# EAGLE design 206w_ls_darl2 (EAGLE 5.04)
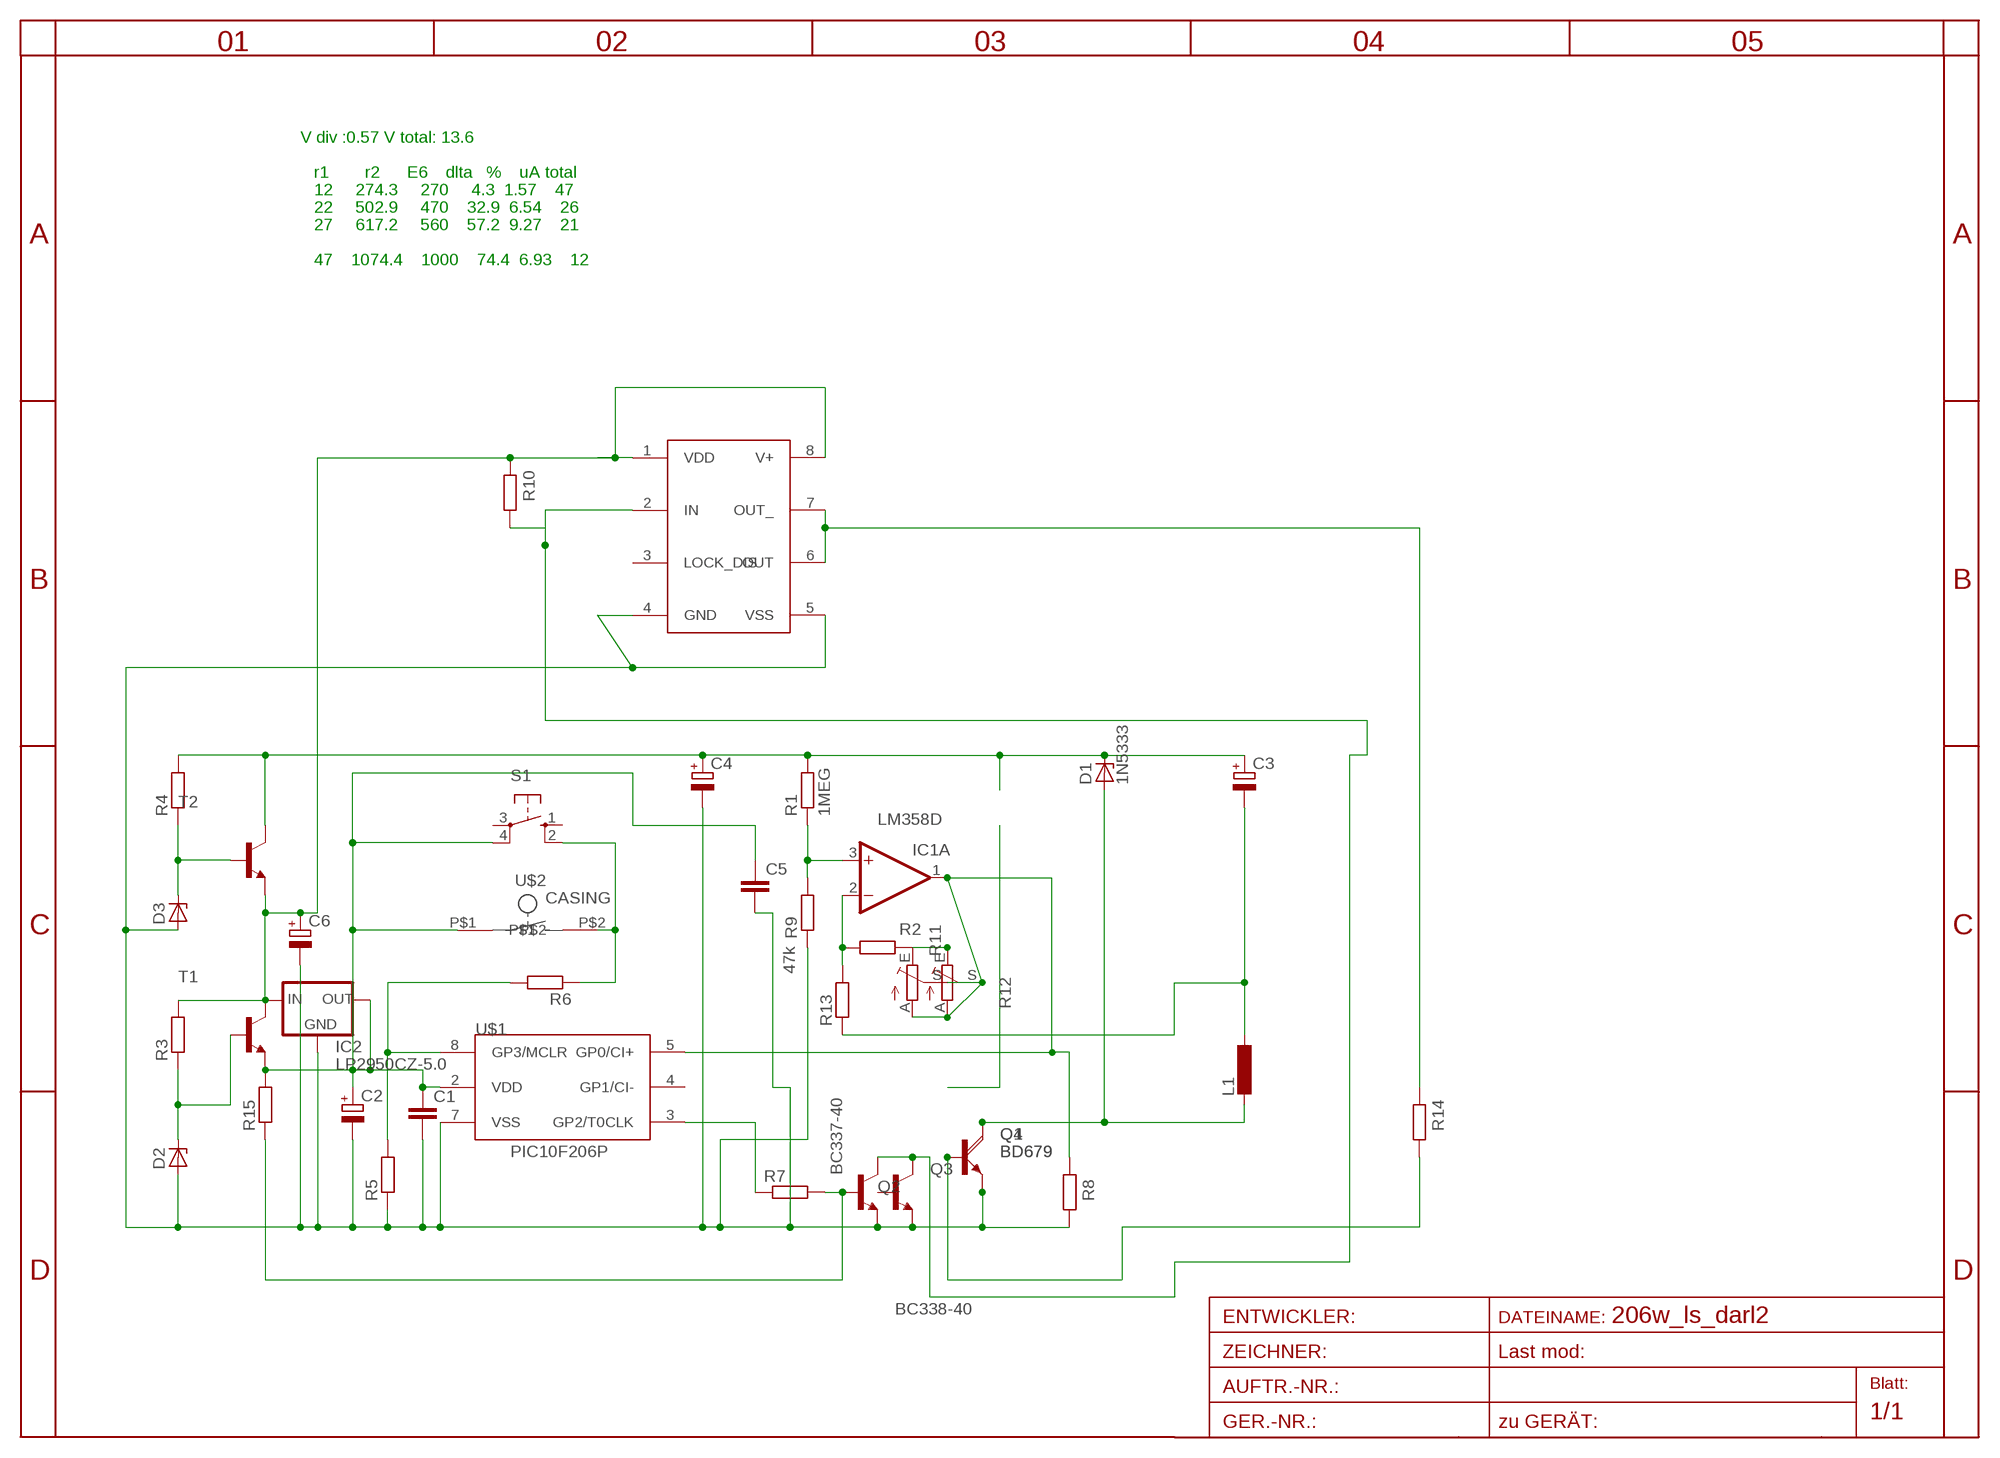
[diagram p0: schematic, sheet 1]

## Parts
C1  C-EU025-025X050  [C025-025X050]
C2  CPOL-EUE3.5-8  [E3,5-8]
C3  CPOL-EUE5-8.5  [E5-8,5]
C4  CPOL-EUE5-8.5  [E5-8,5]
C5  C-EU050-024X044  [C050-024X044]
C6  CPOL-EUE3.5-8  [E3,5-8]
D1  1N5333  [C1702-15]
D2  ZENER-DIODEZD-7.5  [ZDIO-7.5]
D3  ZENER-DIODEZD-7.5  [ZDIO-7.5]
IC1  LM358D  [SO08]
IC2  LP2950CZ-5.0  [TO92]
IC3  TC4432X  [SO-08]
L1  L-EU0207/10  [0207/10]
Q1  BD679  [TO126AV]
Q2  BC337-40  [TO92]
Q3  BC338-40  [TO92-EBC]
Q4  BD679  [TO126AV]
R1  1MEG  R-EU_0207/12  [0207/12]
R2  R-EU_0204/7  [0204/7]
R3  R-EU_0204/7  [0204/7]
R4  R-EU_0207/10  [0207/10]
R5  R-EU_0204/7  [0204/7]
R6  R-EU_0204/7  [0204/7]
R7  R-EU_0207/15  [0207/15]
R8  R-EU_0204/7  [0204/7]
R9  47k  R-EU_0204/7  [0204/7]
R10  R-EU_0204/7  [0204/7]
R11  TRIM_EU-CA6V  [CA6V]
R12  TRIM_EU-LI15  [LI15]
R13  R-EU_0207/40  [0207/40]
R14  R-EU_0204/2V  [0204V]
R15  R-EU_0204/5  [0204/5]
S1  10-XX  [B3F-10XX]
T1  -NPN-TO92-BCE  [TO92-BCE]
T2  -NPN-TO92-BCE  [TO92-BCE]
U$1  PIC10F206P  [DIL8]
U$2  CASING  [CASING]

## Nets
BB: IC3.2(IN) Q2.3(C) Q3.C R10.1
HOTSPOT: D1.A L1.2 Q1.C Q4.C
N$1: IC1.1(A:OUT) R8.2 R11.A R11.S R12.A R12.S U$1.5(GP0/CI+)
N$2: R2.1 R11.E R12.E
N$3: Q1.B Q4.B R14.1
N$5: R5.2 R6.2 U$1.8(GP3/MCLR)
N$6: D2.C R3.1 T1.B
N$7: R6.1 S1.2(S1) U$2.P$2
N$8: IC1.3(A:+IN) R1.1 R9.2
N$9: R7.1 U$1.3(GP2/T0CLK)
N$10: Q2.2(B) R7.2 R15.1
N$11: IC3.6(OUT) IC3.7(OUT_) R14.2
N$12: D3.C R4.1 T2.B
N$15: IC1.2(A:-IN) R2.2 R13.2
V60: C3.+ C4.+ D1.C R1.2 R4.2 T2.C
V+: C1.1 C2.+ C5.1 IC2.1(OUT) R15.2 S1.4(P1) T1.E U$1.2(VDD) U$2.P$1
V-: C1.2 C2.- C4.- C5.2 C6.- D2.A D3.A IC2.2(GND) IC3.4(GND) IC3.5(VSS) Q1.E Q2.1(E) Q3.E Q4.E R5.1 R8.1 R9.1 U$1.7(VSS)
VCC: C6.+ IC2.3(IN) IC3.1(VDD) IC3.8(V+) R3.2 R10.2 T1.C T2.E
VOUT: C3.- L1.1 R13.1
Unconnected: IC1.5(B:+IN) IC1.6(B:-IN) IC1.7(B:OUT) IC3.3(LOCK_DIS) Q3.B S1.1(S) S1.3(P) U$1.4(GP1/CI-)

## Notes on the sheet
- V div :0.57 V total: 13.6
- r1        r2      E6    dlta   %    uA total
- 12     274.3     270     4.3  1.57    47
- 22     502.9     470    32.9  6.54    26
- 27     617.2     560    57.2  9.27    21
- 47    1074.4    1000    74.4  6.93    12

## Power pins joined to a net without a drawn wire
V+: IC1.8(P:V+)
V-: IC1.4(P:V-)

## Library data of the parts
C1 C5 = rcl:C-EU: CAPACITOR, European symbol
C2-C4 C6 = rcl:CPOL-EU: POLARIZED CAPACITOR, European symbol
D1 = diode-1:1N5333: Z DIODE
D2 D3 = diode-1:ZENER-DIODE: Z-Diode
IC1 = linear4:LM358: OP AMP
IC2 = v-reg:LP2950?*: Source: http://cache.national.com/ds/LP/LP2950.pdf
IC3 = microchip:TC4432
L1 = rcl:L-EU: INDUCTOR, European symbol
Q1 Q4 = transistor-power:BD679: NPN DARLINGTON TRANSISTOR
Q2 = transistor-npn:BC337*: NPN Transistor
Q3 = transistor-npn:BC338*: NPN Transistor
R1-R6 R8-R10 R14 R15 = rcl:R-EU_: RESISTOR, European symbol
R7 R13 = rcl-2:R-EU_: RESISTOR, European symbol
R11 R12 = pot:TRIM_EU-: POTENTIOMETER
S1 = switch-omron:10-XX: OMRON SWITCH
T1 T2 = transistor-neu-to92:*-NPN-: NPN Transistror
U$1 = microchip-5:PIC10F2*: uPC nW 0,25/0,5k Program Flash memory Comparator
U$2 = button:CASING

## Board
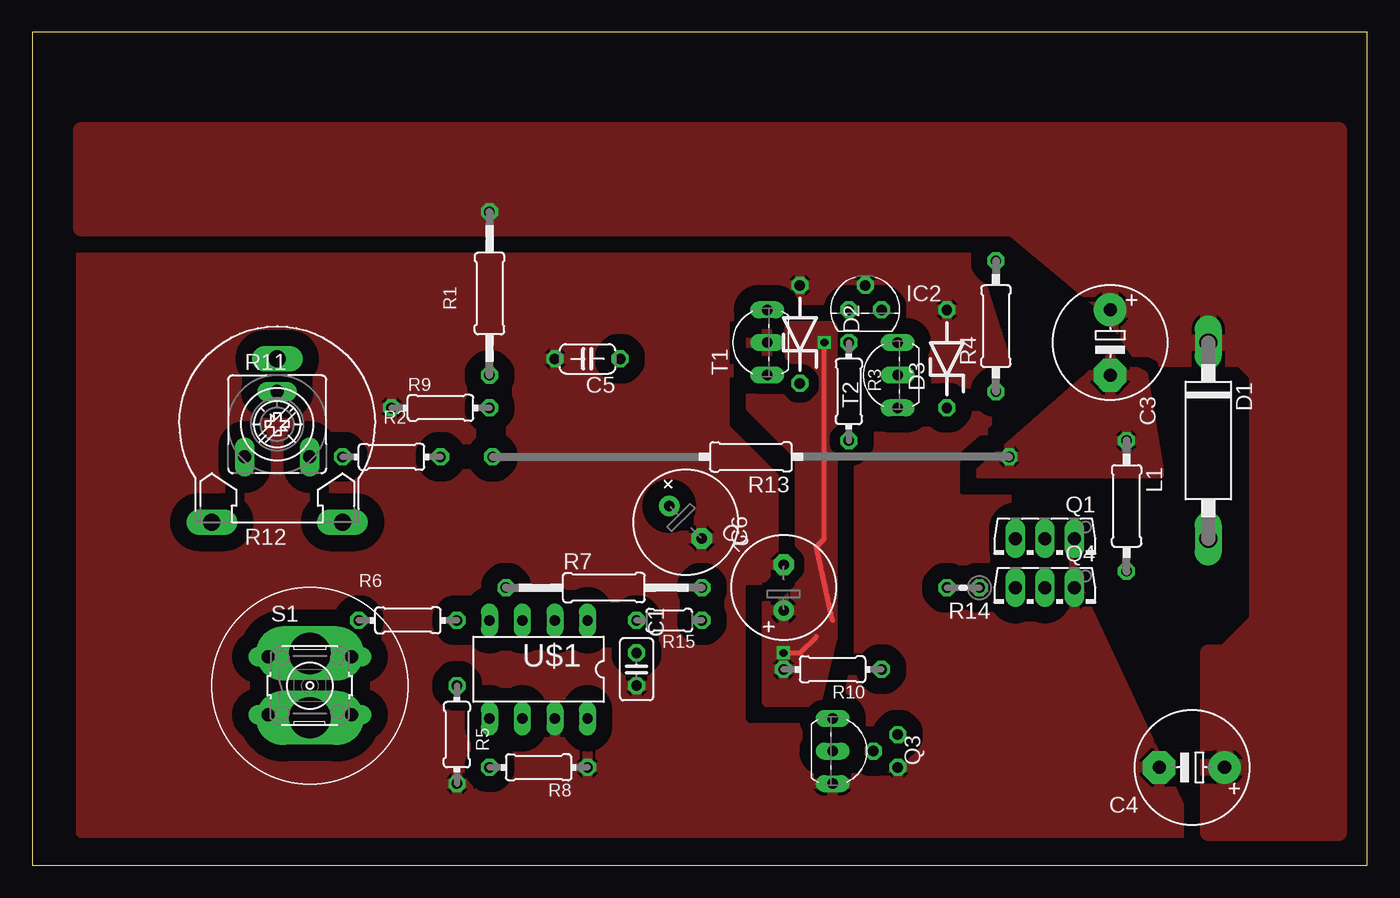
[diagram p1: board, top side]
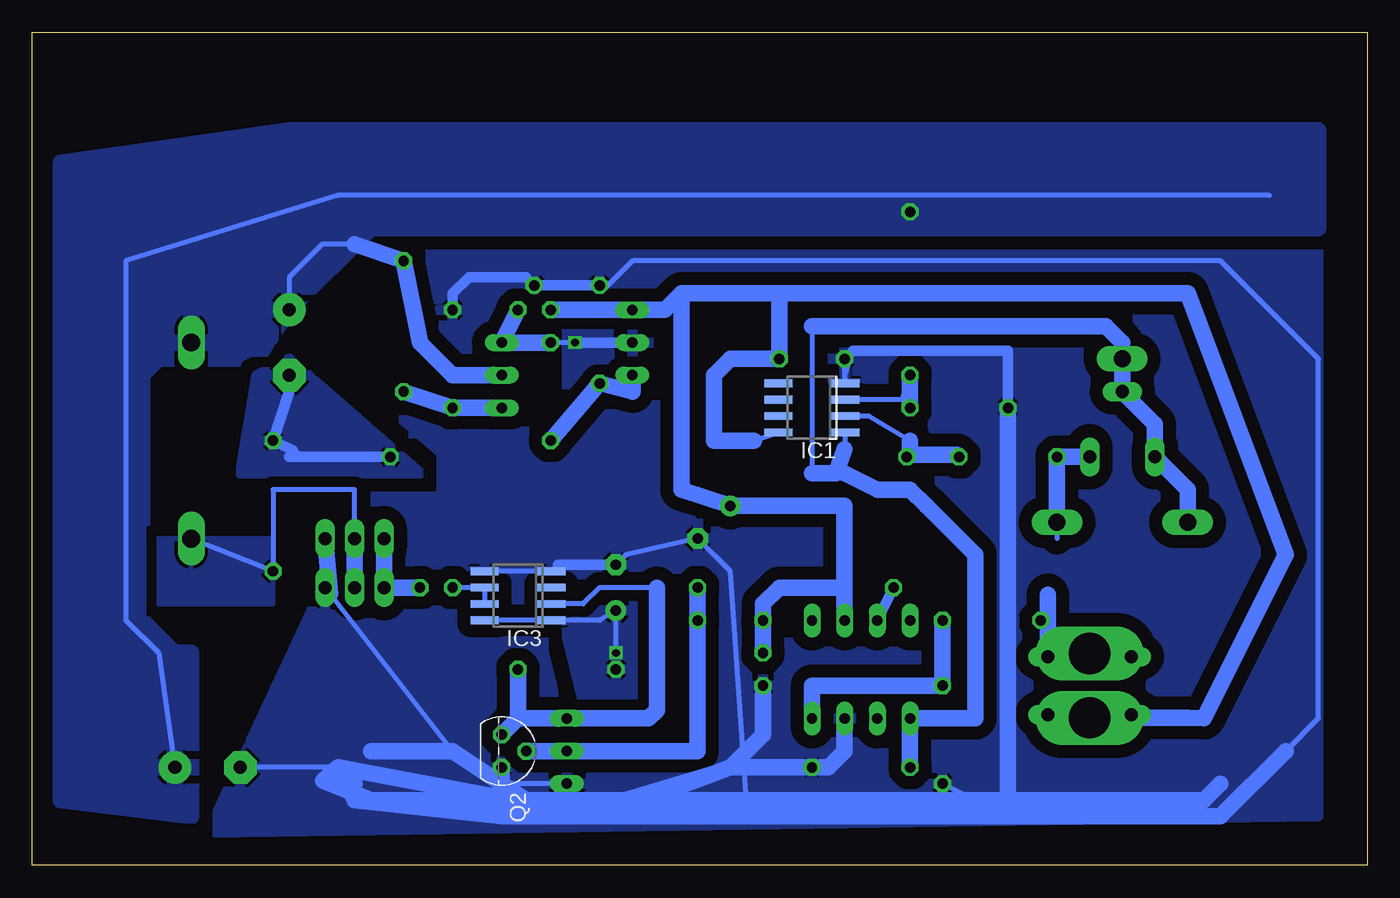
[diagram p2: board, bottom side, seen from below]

Size 103.81 x 64.76 mm. Coordinates in mm from the lower left corner, seen from the top.
Outline: 0,0 103.81,0 103.81,64.76 0,64.76 0,0
Copper layers (1*16): Top 0.035mm / dielectric 1.5mm / Bottom 0.035mm
Design rules "default": minimum track width 10mil, minimum drill 24mil, track to track 8mil, track to pad 8mil, pad to pad 8mil, via to via 8mil, smd to smd 8mil, copper to edge 40mil, drill to drill 8mil, minimum pad ring 10mil, minimum via ring 8mil, stop-mask expansion 4mil, vias tented up to drill 0mil, thermal gap 10mil

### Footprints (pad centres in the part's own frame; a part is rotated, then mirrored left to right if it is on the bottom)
C025-025X050 = drill 0.813 octagon: 1 -1.27,0; 2 1.27,0
E3,5-8 = drill 0.813 pad 1.6 round: + -1.778,0 | drill 0.813 pad 1.6 octagon: - 1.778,0
E5-8,5 = drill 1.016 pad 2.54 round: + -2.54,0 | drill 1.016 pad 2.54 octagon: - 2.54,0
C050-024X044 = drill 0.813 octagon: 1 -2.54,0; 2 2.54,0
C1702-15 = drill 1.397 long: A 7.62,0; C -7.62,0
ZDIO-7.5 = drill 0.813 octagon: A 3.81,0; C -3.81,0
SO08 = smd 0.6 x 2.2: 1 -1.905,-2.6; 2 -0.635,-2.6; 3 0.635,-2.6; 4 1.905,-2.6; 5 1.905,2.6; 6 0.635,2.6; 7 -0.635,2.6; 8 -1.905,2.6
TO92 = drill 0.813 octagon: 1 -1.27,0; 2 0,1.905; 3 1.27,0
SO-08 = smd 0.6 x 2.2: 1 -1.905,-2.6; 2 -0.635,-2.6; 3 0.635,-2.6; 4 1.905,-2.6; 5 1.905,2.6; 6 0.635,2.6; 7 -0.635,2.6; 8 -1.905,2.6
0207/10 = drill 0.813 octagon: 1 -5.08,0; 2 5.08,0
TO126AV = drill 1.016 long: B 2.286,-1.27; C 0,-1.27; E -2.286,-1.27
TO92' = drill 0.813 octagon: 1 1.27,0; 2 0,1.905; 3 -1.27,0
TO92-EBC = drill 0.813 long: B 0,-1.27; C -2.54,-1.27; E 2.54,-1.27
0207/12 = drill 0.813 octagon: 1 -6.35,0; 2 6.35,0
0204/7 = drill 0.813 octagon: 1 -3.81,0; 2 3.81,0
0207/15 = drill 0.813 octagon: 1 -7.62,0; 2 7.62,0
CA6V = drill 1.016 long: A -2.54,-2.54; E 2.54,-2.54; S 0,2.54
LI15 = drill 1.321 long: A -5.08,-7.62; E 5.08,-7.62; S 0,5.08
0207/40 = drill 0.813 octagon: 1 -20.08,0; 2 20.08,0
0204V = drill 0.813 octagon: 1 -1.27,0; 2 1.27,0
0204/5 = drill 0.813 octagon: 1 -2.54,0; 2 2.54,0
B3F-10XX = drill 1.016 long: 1 -3.251,2.261; 2 3.251,2.261; 3 -3.251,-2.261; 4 3.251,-2.261
TO92-BCE = drill 0.813 long: B -2.54,0; C 0,0; E 2.54,0
DIL8 = drill 0.813 long: 1 -3.81,-3.81; 2 -1.27,-3.81; 3 1.27,-3.81; 4 3.81,-3.81; 5 3.81,3.81; 6 1.27,3.81; 7 -1.27,3.81; 8 -3.81,3.81
CASING = drill 3.2 pad 3.81 long: P$1 -2.5,0; P$2 2.5,0

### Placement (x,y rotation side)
C1  46.99,15.24 270 top
C2  50.8,26.67 315 top
C3  83.82,40.64 270 top
C4  90.17,7.62 180 top
C5  43.18,39.37 180 top
C6  58.42,21.59 90 top
D1  91.44,33.02 270 top
D2  59.69,41.27 90 top
D3  71.12,39.37 90 top
IC1  43.18,35.56 90 bottom
IC2  64.77,43.18 0 top
IC3  66.04,20.95 90 bottom
L1  85.09,27.94 270 top
Q1  78.74,24.13 180 top
Q2  BC337-40  [TO92']  67.31,8.89 270 bottom
Q3  63.5,8.89 270 top
Q4  78.74,20.32 180 top
R1  35.56,44.45 90 top
R2  27.94,31.75 0 top
R3  63.5,36.83 90 top
R4  74.93,41.91 90 top
R5  33.02,10.16 90 top
R6  29.21,19.05 0 top
R7  44.45,21.59 0 top
R8  39.37,7.62 180 top
R9  31.75,35.56 0 top
R10  62.23,15.24 180 top
R11  19.05,34.29 0 top
R12  19.05,34.29 0 top
R13  55.88,31.75 180 top
R14  72.39,21.59 180 top
R15  49.53,19.05 180 top
S1  21.59,13.97 0 top
T1  57.15,40.64 90 top
T2  67.31,38.1 90 top
U$1  39.37,15.24 180 top
U$2  21.59,13.97 90 top

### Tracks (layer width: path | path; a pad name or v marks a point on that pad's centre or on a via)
BB
  Bottom 0.406: IC3.2 60.96,20.32 59.69,21.59 55.24,21.59
  Bottom 1.27: 66.04,11.43 Q3.C 55.88,11.43 55.24,12.06 55.24,21.59 | 66.04,11.43 Q2.3 | 66.04,11.43 R10.1
HOTSPOT
  Bottom 0.406: D1.A L1.2 85.09,29.21 78.74,29.21 Q1.C | Q4.C 78.74,20.32
  Bottom 1.27: Q4.C Q1.C
  pour Bottom (isolate 0.813, rank 3): 85.09,25.4 93.98,25.4 93.98,20.32 85.09,20.32
N$1
  Bottom 0.406: 43.18,41.91 43.18,30.48 | R12.S 19.05,40.64 | 40.64,32.34 40.64,31.75 | 40.64,31.75 40.64,30.48 | IC1.1 40.58,31.81 40.64,31.75
  Bottom 1.27: 43.18,41.91 20.32,41.91 19.05,40.64 | 40.64,30.48 38.1,29.21 35.56,29.21 34.29,27.94 30.48,24.13 30.48,11.43 U$1.5 R8.2 | R12.A 13.97,29.21 R11.A 16.51,34.29 R11.S R12.S | 43.18,30.48 41.32,30.48 40.64,32.34
N$2
  Bottom 0.406: R12.E 24.13,25.4
  Bottom 1.27: R11.E R2.1 R12.E
N$3
  Bottom 1.27: R14.1 Q4.B Q1.B
N$5
  Bottom 1.27: U$1.8 43.18,13.97 R5.2 R6.2
N$6
  Bottom 1.27: R3.1 D2.C 57.15,36.83 T1.B
N$7
  Bottom 0.406: 24.84,21.03 24.84,19.61 R6.1
  Bottom 1.27: 24.84,21.03 S1.2 21.83,16.23 U$2.P$2
N$8
  Bottom 0.406: IC1.3 36.2,36.2 R1.1
  Bottom 1.27: R9.2 R1.1
N$9
  Bottom 0.813: R7.1 U$1.3
N$10
  Bottom 0.406: R15.1 R7.2
  Bottom 1.27: Q2.2 52.07,8.89 R15.1 R7.2
N$11
  Bottom 0.406: R14.2 IC3.6 IC3.7
N$12
  Bottom 0.406: D3.C R4.1
  Bottom 1.27: T2.B D3.C R4.1
N$15
  Bottom 0.406: IC1.2 38.73,34.92 35.56,33.02 | 35.56,31.91 R13.2 | R2.2 31.91,31.91
  Bottom 1.27: 35.56,33.02 35.56,31.91 31.91,31.91
V60
  Bottom 0.406: C4.+ 93.98,16.51 96.52,19.05 96.52,46.99 80.01,52.07 7.62,52.07 | 78.74,48.26 81.28,48.26 83.82,45.72 C3.+
  Bottom 1.27: 78.74,48.26 R4.2 73.66,40.64 71.12,38.1 T2.C
  pour Bottom (isolate 0.813, rank 4): 3.81,57.15 83.82,57.15 101.6,54.61 101.6,5.08 91.44,3.81 91.44,16.51 92.71,16.51 95.25,19.05 95.25,38.1 93.98,39.37 86.36,39.37 83.82,43.18 77.47,49.53 3.81,49.53
  pour Top (isolate 0.813, rank 4): 3.81,57.15 101.6,57.15 101.6,2.54 91.44,2.54 91.44,16.51 92.71,16.51 95.25,19.05 95.25,38.1 93.98,39.37 86.36,39.37 83.82,43.18 76.2,49.53 3.81,49.53
V+
  Bottom 0.406: 47.69,33.02 IC1.8 | 54.61,43.18 T1.E | C2.+ | C2.+ | U$2.P$1 24.6,11.47 S1.4
  Bottom 1.27: 40.64,21.59 U$1.2 | 53.34,44.45 53.34,29.21 C2.+ 40.64,27.94 40.64,21.59 | 45.72,44.45 13.97,44.45 6.35,24.13 12.7,11.43 13.97,11.47 U$2.P$1 | 45.72,44.45 53.34,44.45 | C1.1 R15.2 46.99,20.32 45.72,21.59 40.64,21.59 | 47.69,33.02 50.8,33.02 50.8,38.1 49.53,39.37 C5.1 45.72,44.45 | 53.34,44.45 54.61,43.18 IC2.1
V-
  Bottom 0.406: 40.01,40.01 40.64,38.1 IC1.4 40.64,38.8 C5.2 | 30.48,5.08 R5.1 | 49.53,7.62 50.8,7.62 63.5,3.81 | Q3.E 67.31,6.35 | 71.12,8.89 80.64,21.1 Q4.E | 80.01,7.62 C4.- | 78.74,6.35 81.41,6.35 81.19,6.57 | D2.A 59.05,45.09 57.15,46.99 11.43,46.99 3.81,39.37 3.81,11.43 6.35,8.89 | 59.69,3.81 48.26,5.08 49.53,22.86 50.81,24.14 C2.- 57.65,24.14 C6.- | 62.93,23.37 IC3.4 IC3.5 | IC2.2 65.41,45.72
  Bottom 0.813: 40.01,40.01 27.94,40.01 R9.1 | D2.A IC2.2 | C6.- 62.93,23.37 | D3.A 71.12,44.45 69.85,45.72 65.41,45.72
  Bottom 1.27: 6.35,8.89 11.43,3.81 27.94,3.81 | 27.94,3.81 59.69,3.81 | 59.69,3.81 63.5,3.81 | 63.5,3.81 67.31,3.81 78.74,5.08 80.01,7.62 | 67.31,6.35 Q2.1 | 11.43,6.35 12.7,5.08 30.48,5.08 48.26,5.08 77.47,5.08 81.19,6.57 80.01,7.62 | 80.01,7.62 78.74,6.35 | U$1.7 40.64,8.89 41.91,7.62 R8.1 49.53,7.62 | 59.69,3.81 80.01,7.62 | 59.69,3.81 49.53,7.62 | 63.5,3.81 Q3.E | 63.5,3.81 71.12,8.89 77.47,8.89 | C1.2 46.99,10.16 49.53,7.62 | 27.94,3.81 R9.1 | 80.64,21.1 Q1.E
  pour Bottom (isolate 1.016, rank 5): 72.39,49.53 81.28,21.59 90.17,2.54 3.81,3.81 3.81,48.26
  pour Top (isolate 1.27, rank 5): 72.39,49.53 81.28,21.59 90.17,2.54 3.81,2.54 3.81,49.53
VCC  (via drill 0.6)
  Top 0.406: v58.42,16.51 59.69,16.51 60.96,17.78 | v61.59,40.64 61.59,25.4 60.96,24.77 62.23,19.05
  Bottom 0.406: v58.42,16.51 58.42,17.78 C6.+ 59.69,19.05 IC3.1 IC3.8 | v61.59,40.64 R3.2
  Bottom 0.813: v61.59,40.64 T1.C
  Bottom 1.27: IC2.3 T2.E R3.2
  pour Top (isolate 0.813): 55.88,41.91 62.23,41.91 62.23,17.78 60.96,12.7 57.15,12.7 57.15,20.32 58.42,20.32 59.69,21.59 59.69,31.75 55.88,35.56
  pour Bottom (isolate 0.813): 55.88,41.91 62.23,41.91 62.23,17.78 60.96,12.7 57.15,12.7 57.15,20.32 58.42,20.32 59.69,21.59 59.69,31.75 55.88,35.56
VOUT
  Bottom 0.406: 82.55,31.75 83.57,32.26 83.82,32 83.82,31.75 | 83.82,36.83 C3.-
  Bottom 0.813: 83.57,32.26 L1.1 83.82,36.83 | R13.1 83.82,31.75
  pour Top (isolate 0.813): 83.82,39.37 86.36,38.1 87.63,30.48 73.66,30.48
  pour Bottom (isolate 0.813): 83.82,39.37 86.36,38.1 87.63,30.48 73.66,30.48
